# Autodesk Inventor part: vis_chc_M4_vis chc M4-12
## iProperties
Shininess: 64.0
Length Units: 11269
Angle Units: 11279
Time Units: 11290
Mass Units: 11283
Length Display Precision: 3
Angle Display Precision: 2
Compacted: True
Part Number: vis_chc_M4_vis chc M4-12
Document SubType Name: Modeling
Created: 2006-01
Material: Par défaut
Designer: riri
Density: 0.0
Volumn: 0.0
Area: 0.0
PropertySet Name: Model Information
Control State: 0
Master: False
Checked Out: False
Author: riri
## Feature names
1. Base1
